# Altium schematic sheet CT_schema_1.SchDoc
size 463 x 258 mm
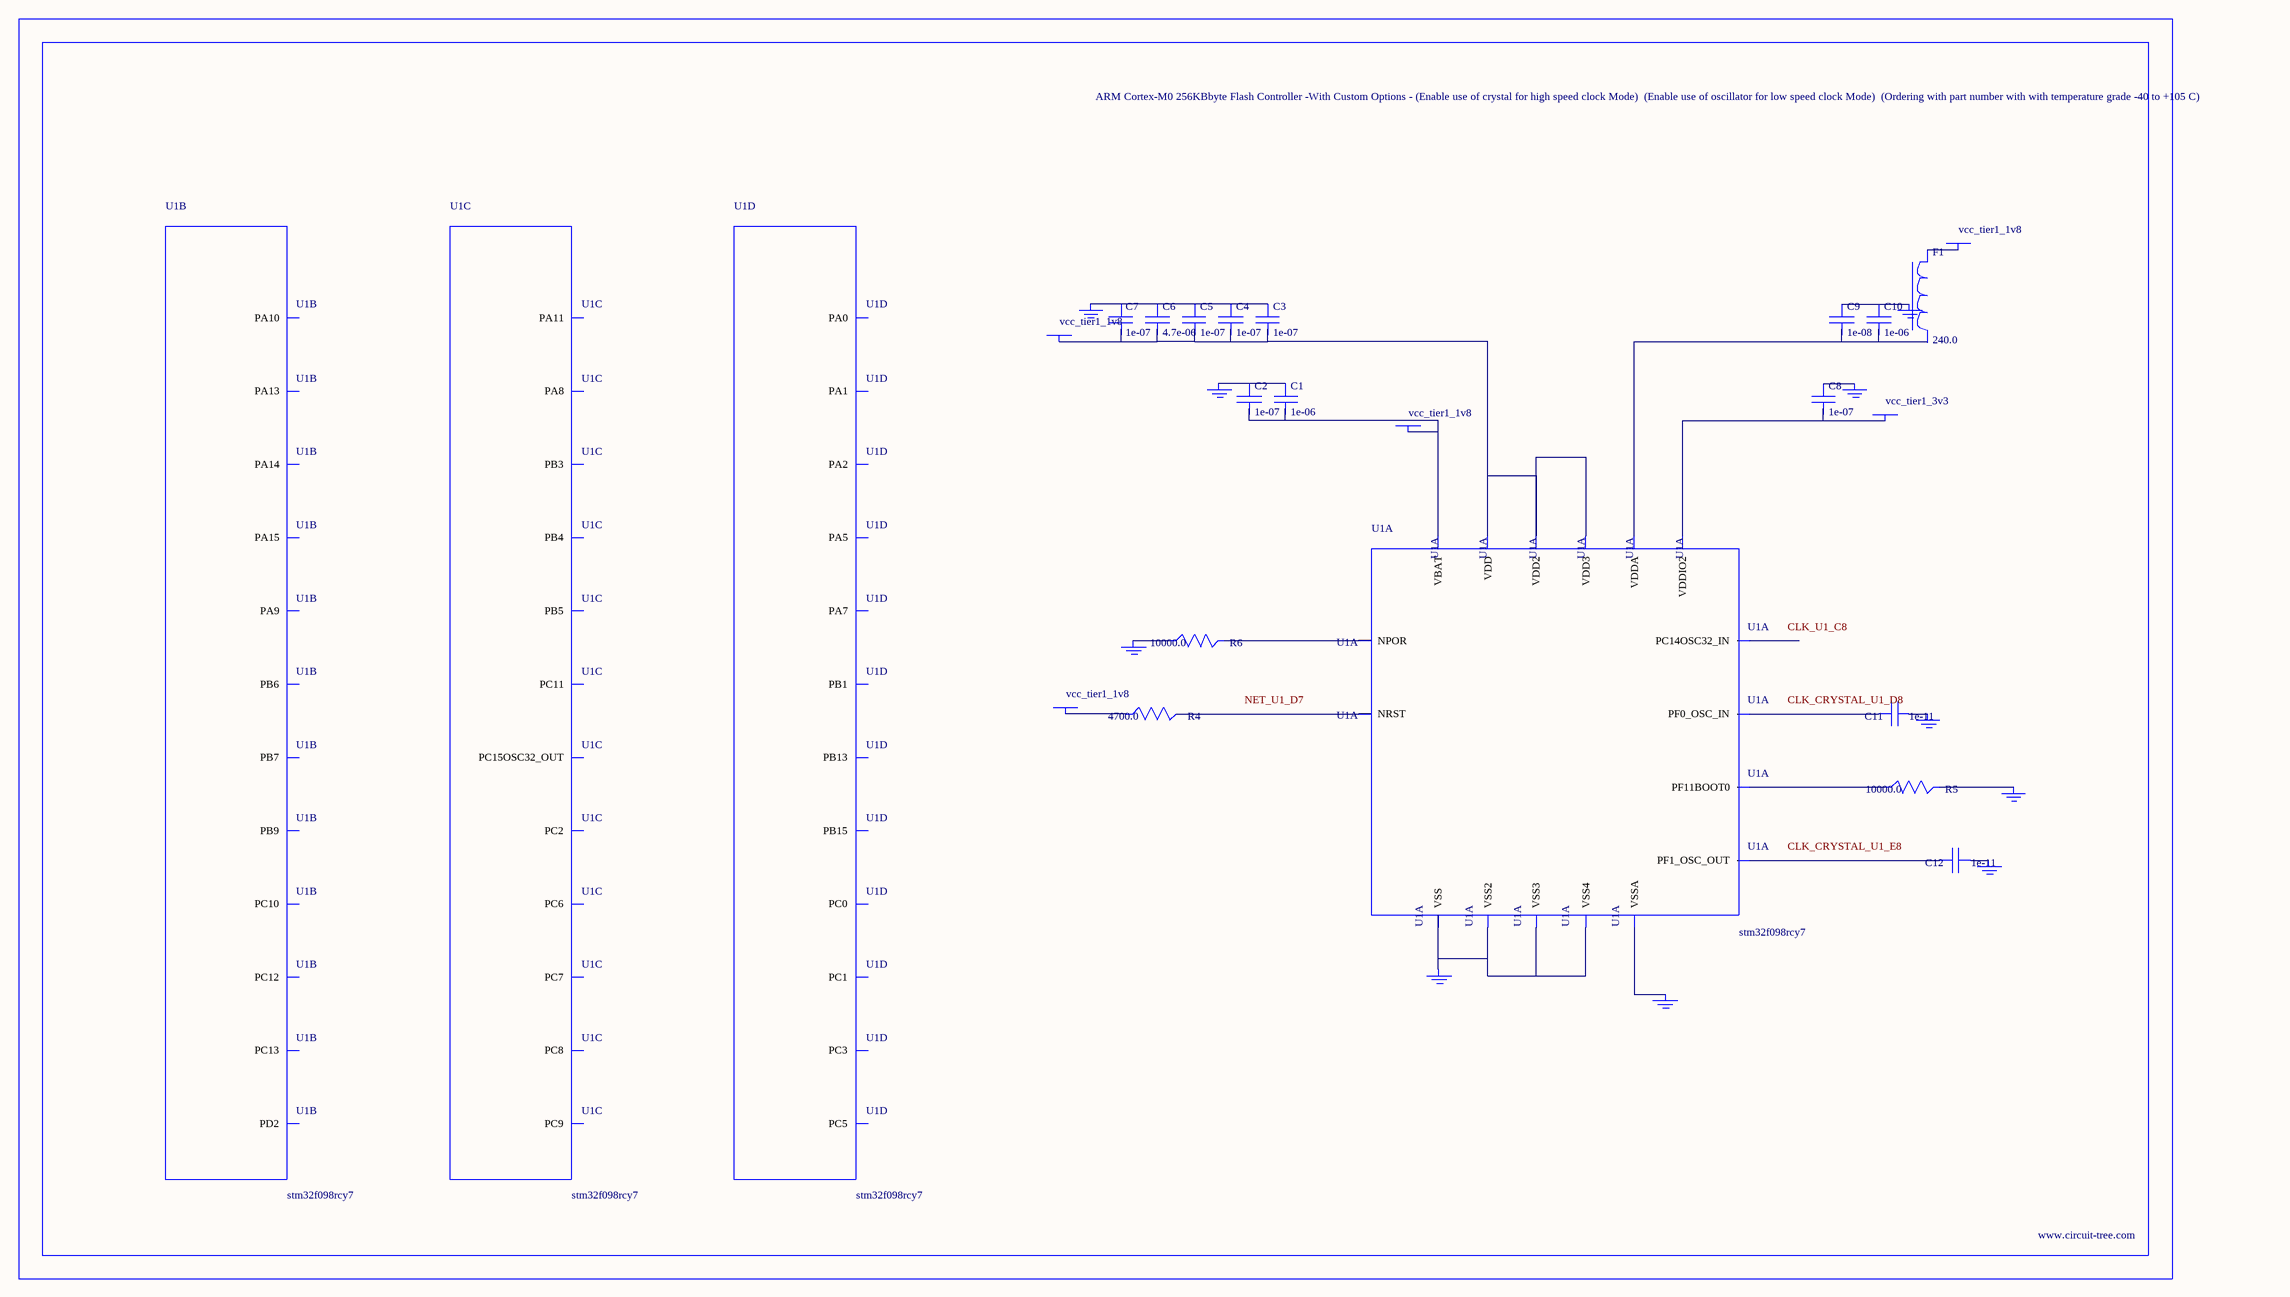
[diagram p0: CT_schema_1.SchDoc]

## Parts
BORDER0  (no value)
C1  1e-06  [C0603]
C2  1e-07  [C0603]
C3  1e-07  [C0603]
C4  1e-07  [C0603]
C5  1e-07  [C0603]
C6  4.7e-06  [C0603]
C7  1e-07  [C0603]
C8  1e-07  [C0603]
C9  1e-08  [C0603]
C10  1e-06  [C0603]
C11  1e-11  [C0402]
C12  1e-11  [C0402]
F1  240.0  [L0603]
GND_INSTANCE_0_0  (no value)
GND_INSTANCE_0_1  (no value)
GND_INSTANCE_0_2  (no value)
GND_INSTANCE_0_3  (no value)
GND_INSTANCE_0_4  (no value)
GND_INSTANCE_0_5  (no value)
GND_INSTANCE_0_6  (no value)
GND_INSTANCE_0_7  (no value)
GND_INSTANCE_0_8  (no value)
GND_INSTANCE_0_9  (no value)
POWER_INSTANCE_0_0  vcc_tier1_1v8
POWER_INSTANCE_0_1  vcc_tier1_1v8
POWER_INSTANCE_0_2  vcc_tier1_1v8
POWER_INSTANCE_0_3  vcc_tier1_3v3
POWER_INSTANCE_0_4  vcc_tier1_1v8
R4  4700.0  [R0603]
R5  10000.0  [R0603]
R6  10000.0  [R0603]
U1  stm32f098rcy7  [WLCSP64]  (parts A,B,C,D of 5)

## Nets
NetC1_1: C1.1 C2.1 GND_INSTANCE_0_0.0(GND)
NetC1_2: C1.2 C2.2 POWER_INSTANCE_0_0.0(PWR) U1.B8(VBAT)
NetC3_1: C3.1 C4.1 C5.1 C6.1 C7.1 GND_INSTANCE_0_2.0(GND)
NetC3_2: C3.2 C4.2 C5.2 C6.2 C7.2 POWER_INSTANCE_0_2.0(PWR) U1.A8(VDD) U1.G6(VDD2) U1.H1(VDD3)
NetC8_1: C8.1 GND_INSTANCE_0_3.0(GND)
NetC8_2: C8.2 POWER_INSTANCE_0_3.0(PWR) U1.A1(VDDIO2)
NetC9_1: C9.1 C10.1 GND_INSTANCE_0_1.0(GND)
NetC9_2: C9.2 C10.2 U1.H8(VDDA)
NetC11_1: C11.1 GND_INSTANCE_0_6.0(GND)
NetC11_2: C11.2 U1.D8(PF0_OSC_IN)
NetC12_1: C12.1 GND_INSTANCE_0_7.0(GND)
NetC12_2: C12.2 U1.E8(PF1_OSC_OUT)
NetF1_1: F1.1 POWER_INSTANCE_0_1.0(PWR)
NetGND_INSTANCE_0_4_0: GND_INSTANCE_0_4.0(GND) R5.2
NetGND_INSTANCE_0_5_0: GND_INSTANCE_0_5.0(GND) R6.1
NetGND_INSTANCE_0_8_0: GND_INSTANCE_0_8.0(GND) U1.G8(VSSA)
NetGND_INSTANCE_0_9_0: GND_INSTANCE_0_9.0(GND) U1.A7(VSS) U1.B2(VSS2) U1.G7(VSS3) U1.H2(VSS4)
NetPOWER_INSTANCE_0_4_0: POWER_INSTANCE_0_4.0(PWR) R4.1
NetR4_2: R4.2 U1.D7(NRST)
NetR5_1: R5.1 U1.C6(PF11BOOT0)
NetR6_2: R6.2 U1.H4(NPOR)

Not connected (* = marked no-connect by the designer): F1 2; U1 A2(PA15) A3(PC10) A4(PD2) A5(PB6) B3(PA14) B4(PC12) B5(PB7) B6(PB9) B7(PC13) C1(PA9) C2(PA10) C3(PA13) C4(PC11) C5(PB5) C7(PC15OSC32_OUT) C8(PC14OSC32_IN) D1(PC7) D2(PA8) D3(PA11) D4(PB3) D5(PB4) D6(PC2) E1(PC6) E2(PC8) E3(PC9) E4(PA7) E5(PA2) E6(PC3) E7(PC0) F1(PB15) F2(PB13) F3(PB1) F4(PC5) F5(PA5) F6(PA1) F7(PA0) F8(PC1)

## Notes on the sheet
- Labels drawn without touching a wire or pin: CLK_CRYSTAL_U1_D8, CLK_CRYSTAL_U1_E8, CLK_U1_C8, NET_U1_D7

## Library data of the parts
BORDER0 = BORDER_PAGE0
C1 C10 = C0603C105K3RACTU
C2-C5 C7 C8 = 06035C104K4Z2A
C6 = GRM188R6YA475KE15D
C9 = 06035C103K4Z2A
C11 C12 = C0402C100K3GACTU
F1 = Z0603C241ASMST
GND_INSTANCE_0_0-GND_INSTANCE_0_9 = GND
POWER_INSTANCE_0_0-POWER_INSTANCE_0_4 = PWR
R4 = RC0603JR-074K7L
R5 R6 = RC0603JR-0710KL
